// Mitsubishi GX Works2 project: 1.起保停   PLC: FX3U/FX3UC

PROGRAM MAIN
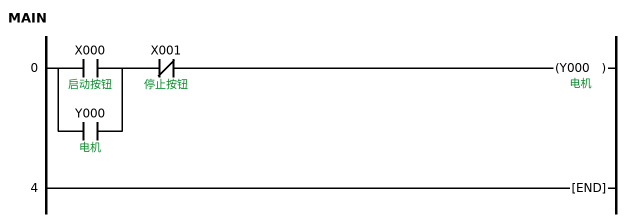
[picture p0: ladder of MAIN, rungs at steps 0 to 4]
0     LD      X000  ; 启动按钮
      OR      Y000  ; 电机
      ANI     X001  ; 停止按钮
      OUT     Y000  ; 电机
4     END
END_PROGRAM
